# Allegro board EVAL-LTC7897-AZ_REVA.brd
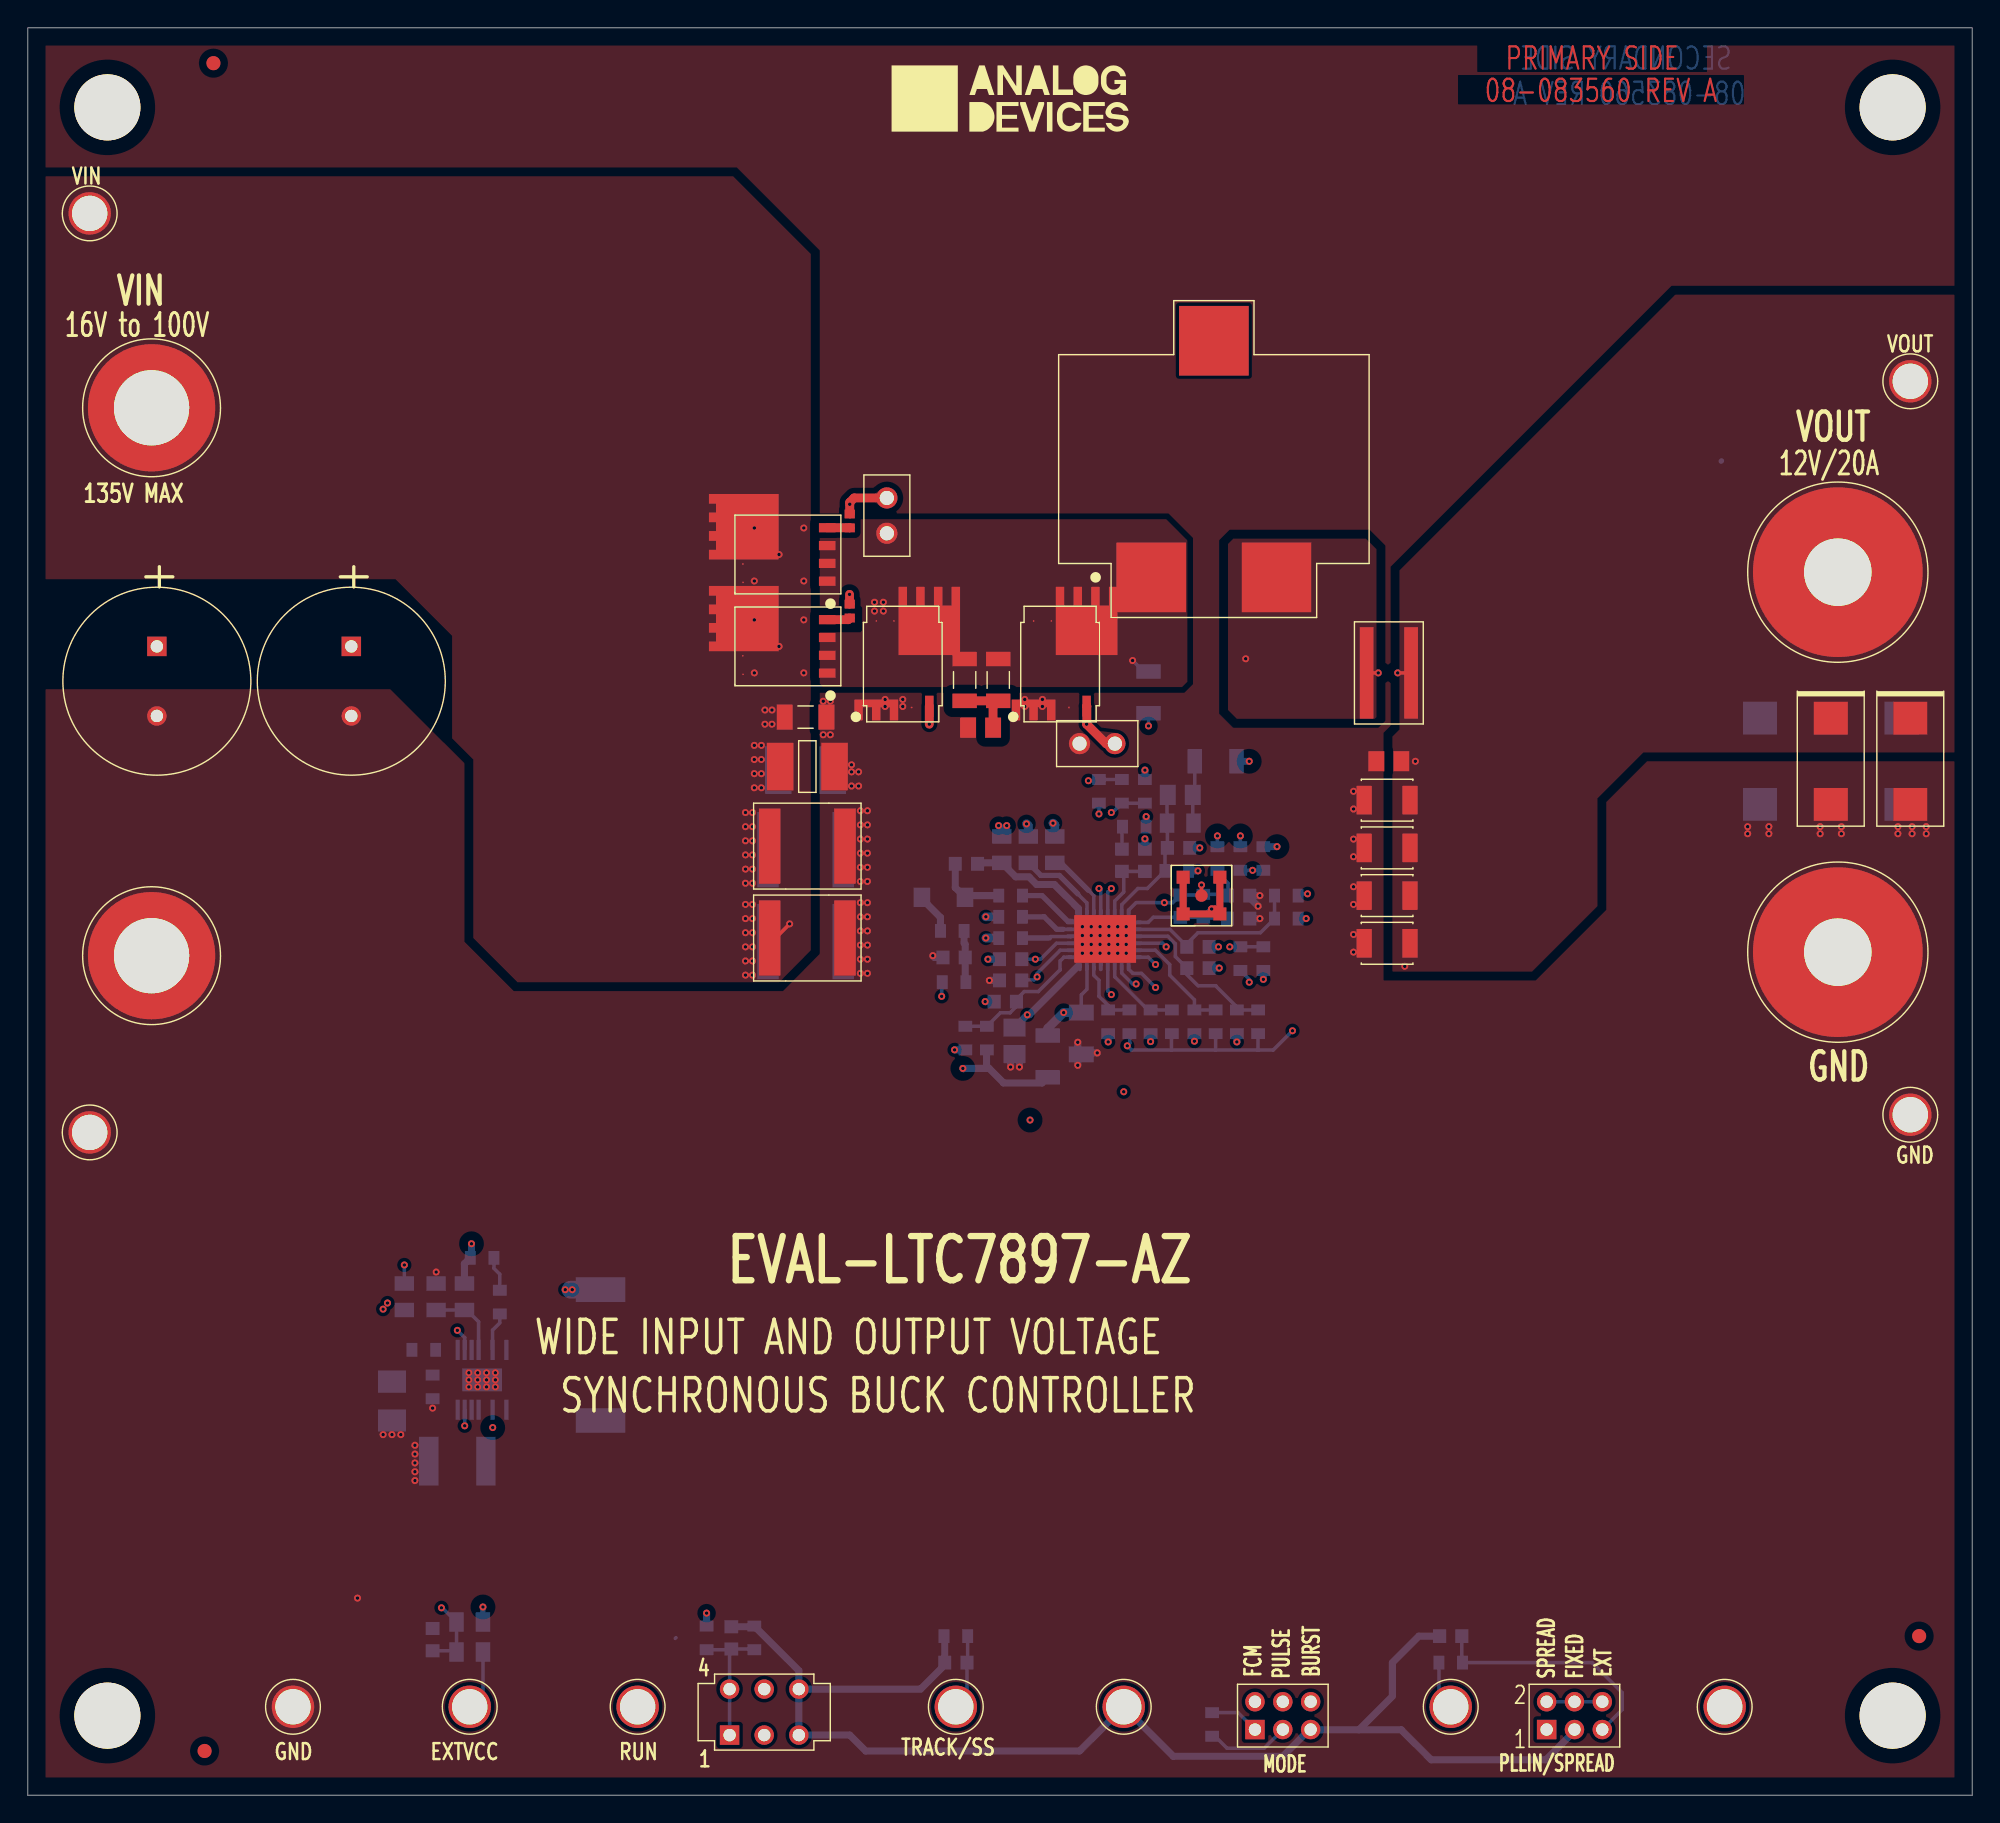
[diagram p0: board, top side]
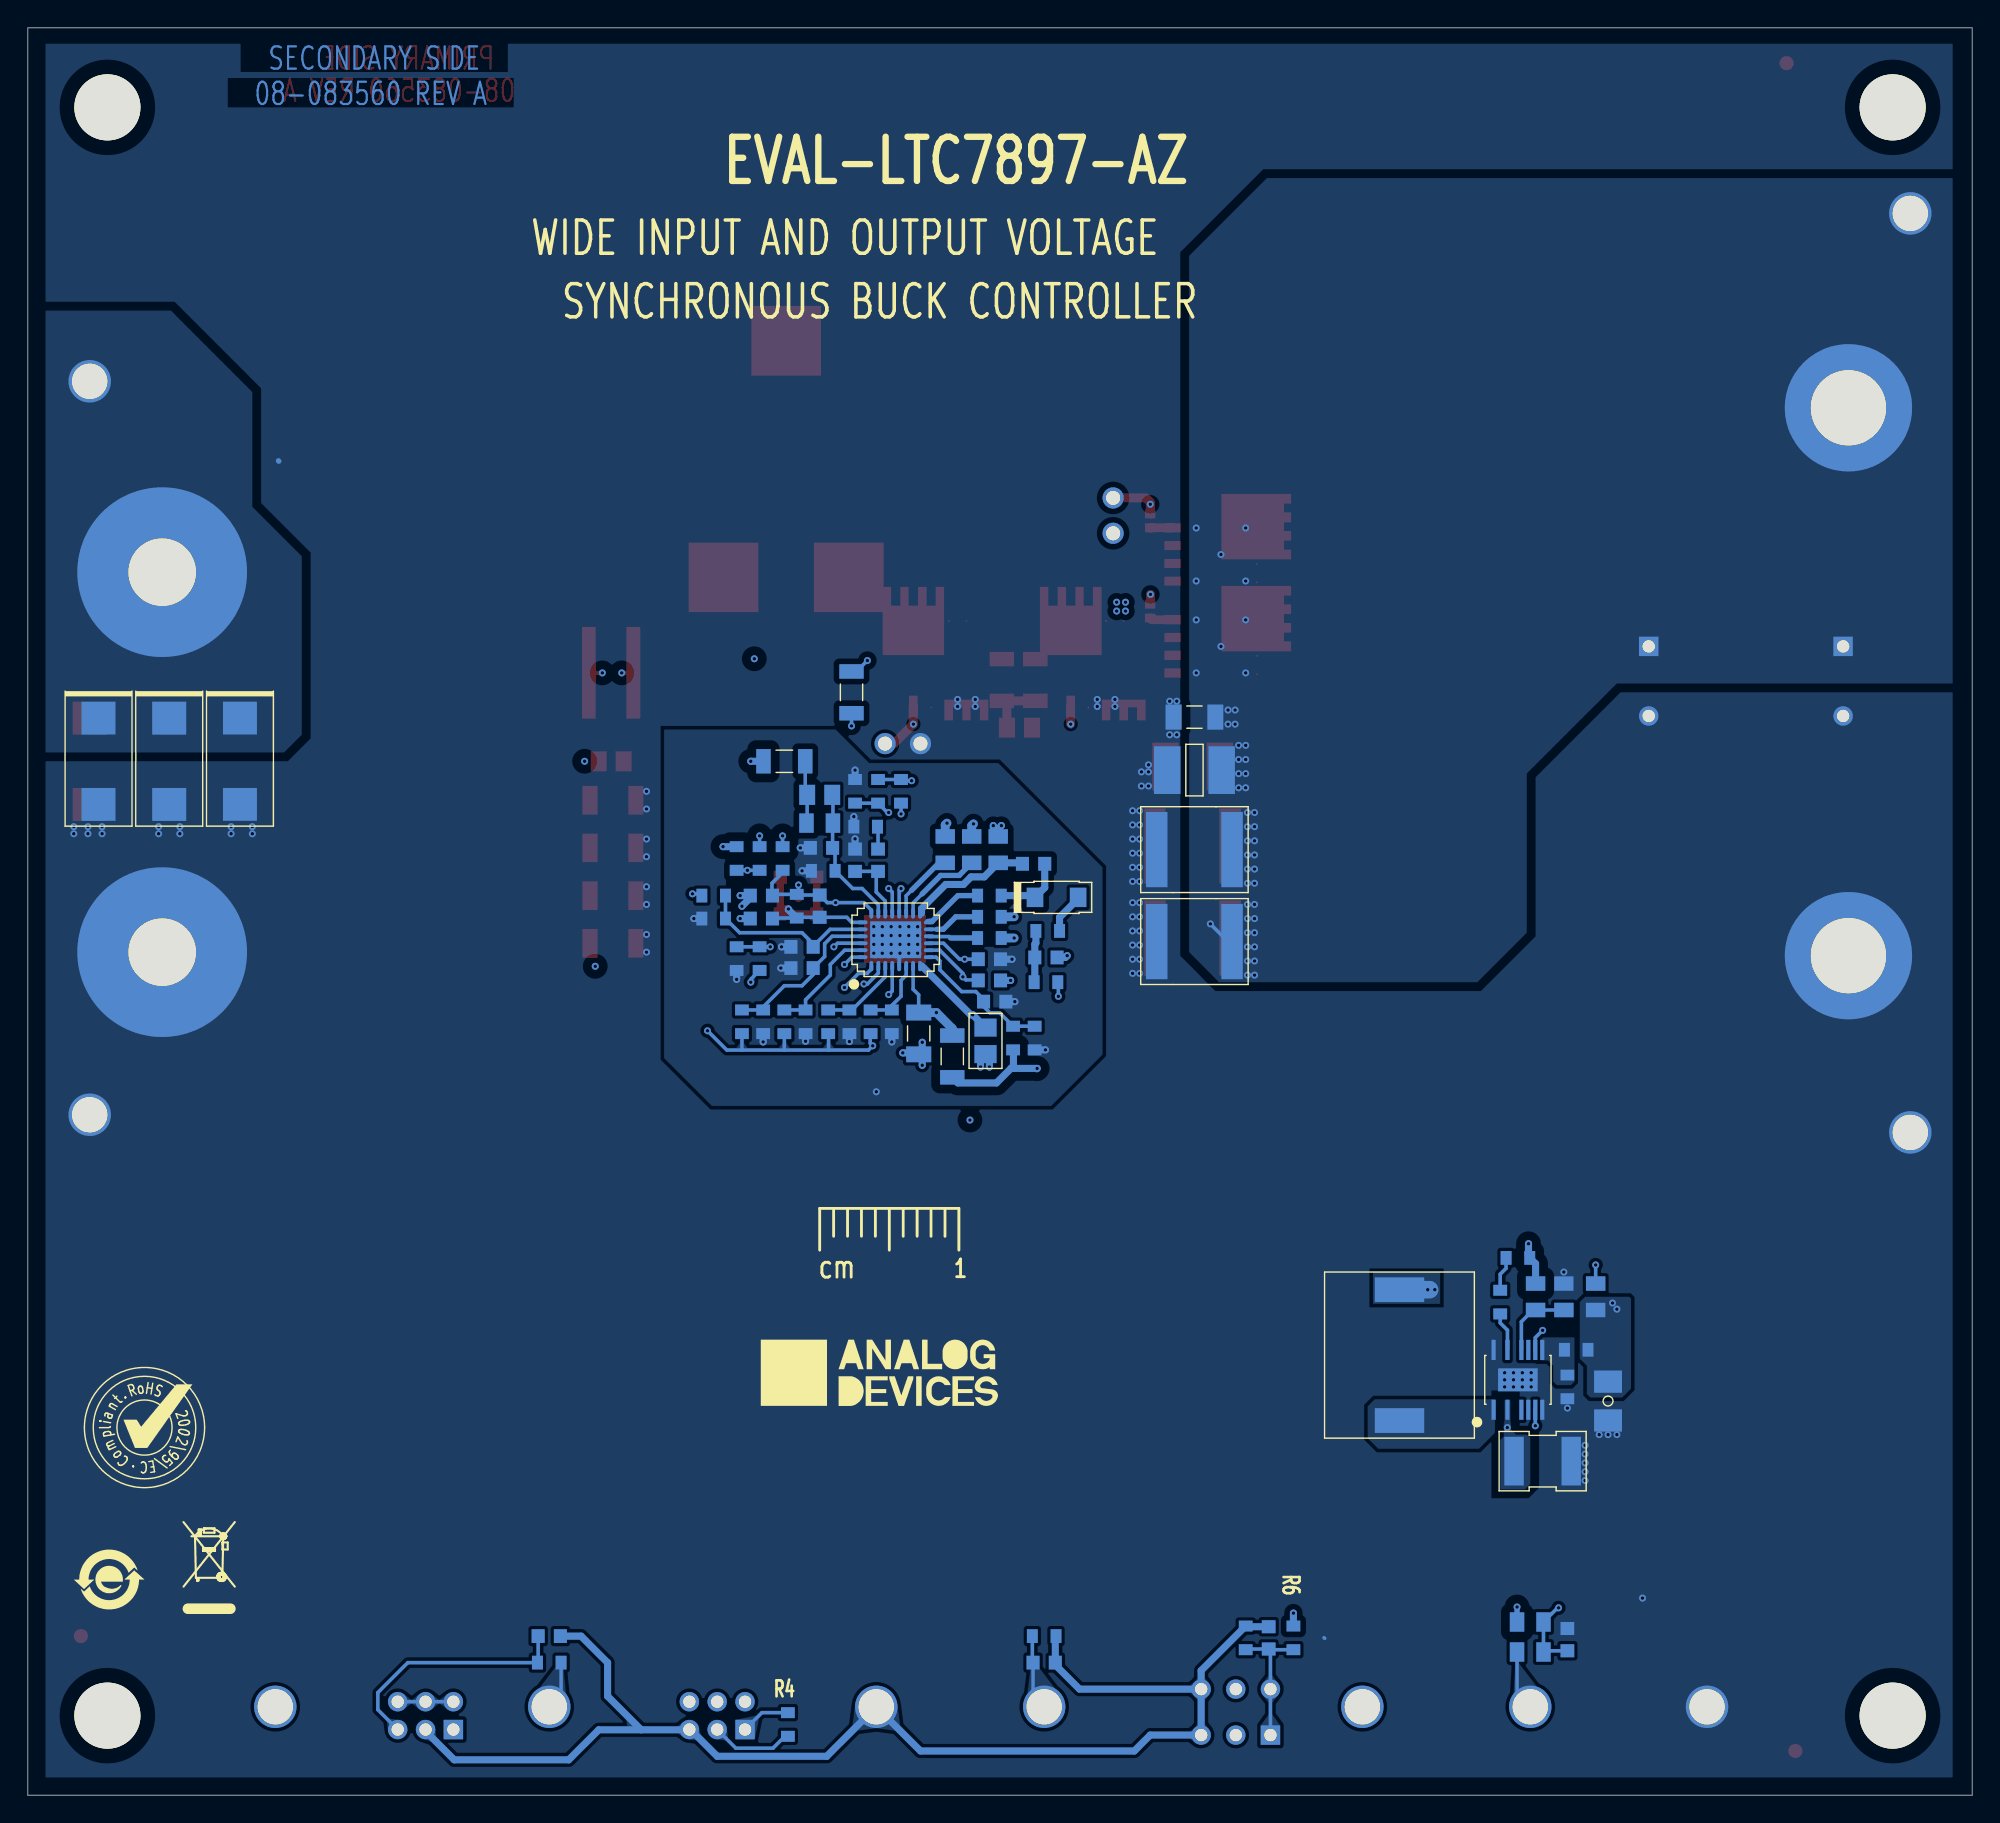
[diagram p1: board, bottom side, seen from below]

Outline 139.7 x 127 mm; copper layers: TOP, LAYER_2, LAYER_3, LAYER_4, LAYER_5, BOTTOM. Coordinates in mm from the lower left corner of the outline.
Outline path: 0,127 0,0 139.7,0 139.7,127 0,127

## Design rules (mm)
constraint set DEFAULT: min track width 0.254
net group _N309: nets _N97 _N309
net group VIN2: nets _N130 VIN2
net group BG: nets BG BG_X BG_X3
net group DRVUV: nets _N98 _N99 _N173 _N192 _N215 DRVUV DTCA DTCB INTVCC VPRG
net group EXTVCC: nets _N148 _N308 EXTVCC SNSN SNSP SW SWN UNNAMED_2_ADLT7809_I6_BOOST UNNAMED_2_ADLTC3639_I1_SW UNNAMED_2_ADLTC3639_I1_VFB UNNAMED_2_CAP_I88_N1 UNNAMED_2_CAP_I169_N1 UNNAMED_2_CNTP1P_I150_N1 UNNAMED_2_IND_I113_N2 VOUT VSOP

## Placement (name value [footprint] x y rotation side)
C1  TBD0603  [C0603]  84.07 59.44 0 bottom
C2  TBD0603  [C0603]  102.23 11.43 180 bottom
C3  47UF  [CPLRAD197D512H846LD24]  23.24 82.55 270 top
C4  0.1uF  [C0603]  66.67 9.53 180 bottom
C5  TBD0603  [C0603]  84.07 60.96 0 bottom
C6  47UF  [CPLRAD197D512H846LD24]  9.27 82.55 270 top
C7  2.2UF  [C2220H106]  56.01 68.2 0 top
C8  2.2UF  [C2220H106]  55.88 67.94 0 bottom
C9  TBD0805  [C0805]  82.8 71.88 180 bottom
C10  TBD0603  [C0603]  82.68 68.07 0 bottom
C11  0.1uF  [C1206]  75.69 54.74 270 bottom
C12  220pF  [C0603]  80.26 67.18 90 bottom
C13  6.8NF  [C0603]  78.61 67.18 90 bottom
C14  1uF  [C0603]  70.61 58.55 180 bottom
C15  4.7uF  [C0805H53]  70.89 54.2 270 bottom
C16  0.1uF  [C0603]  70.61 60.07 180 bottom
C17  1000pF  [C0603]  82.8 63.88 270 bottom
C18  TBD0603  [C0603]  50.55 11.3 90 bottom
C19  0.1uF  [C0603]  67.44 66.93 0 bottom
C20  0.1uF  [C0603]  66.55 60.2 180 bottom
C21  TBD0805  [C0805]  68.45 76.71 180 top
C22  1UF  [C1812H110]  55.88 73.66 0 bottom
C23  0.1uF  [C1206]  55.88 77.47 0 bottom
C24  1uF  [C0603]  29.08 11.18 90 bottom
C25  1UF  [C1812H110]  56.01 73.91 0 top
C26  0.1uF  [C1206]  55.88 77.47 0 top
C27  0.1UF  [C0805]  97.79 74.3 180 top
C28  22uF  [C1210H106]  97.66 71.5 180 top
C29  0.47UF  [C1812H71]  30.86 24 0 bottom
C30  22uF  [C1210H106]  97.66 68.07 180 top
C31  22uF  [C1210H106]  97.66 64.64 180 top
C32  100UF  [C7343-31]  124.46 74.3 270 bottom
C33  22uF  [C1210H106]  97.66 61.21 180 top
C34  100UF  [C7343-31]  129.54 74.3 270 bottom
C35  100UF  [C7343-31]  129.54 74.3 270 top
C36  100UF  [C7343-31]  134.62 74.3 270 bottom
C37  100UF  [C7343-31]  135.25 74.3 270 top
C39  4.7UF  [C1206H71]  26.16 28.32 270 bottom
C41  TBD0603  [C0603]  87 64.64 0 bottom
C42  TBD0603  [C0603]  87 62.99 180 bottom
C43  TBD0603  [C0603]  70.23 57.02 0 bottom
C44  2.2UF  [C2220H106]  56.01 61.59 0 top
C45  2.2UF  [C2220H106]  55.88 61.34 0 bottom
D1  PNE20010ERX  [SOD123W]  65.79 64.52 180 bottom
J1  575-4  [CNBANANAD312LD203]  8.89 99.69 0 top
J2  575-4  [CNBANANAD312LD203]  8.89 60.33 0 top
J3  KFH-032-10ET  [CNPEMKFH-032]  130.05 87.88 0 top
J4  KFH-032-10ET  [CNPEMKFH-032]  130.05 60.58 0 top
J5  0734152063  [CNSMASQ136H203]  84.33 64.64 0 top
JP1  62000621121  [CNTHMHDR2X3L236W157H248]  109.13 4.72 0 top
JP2  62000621121  [CNTHMHDR2X3L236W157H248]  88.17 4.72 0 top
L1  5.5UH  [LSML858W571H571]  85.22 96.01 0 top
L2  470UH  [LSML402W394H201]  41.15 31.62 90 bottom
NOREF  -  []  14.22 254.25 0 top
NOREF#2  -  []  0 127 0 top
NOREF#3  -  []  294.89 163.96 0 top
NOREF#4  -  [unnamed#2]  12.7 3.17 0 top
NOREF#5  -  []  112.39 -34.04 0 top
NOREF#6  -  []  302.51 96.77 0 top
NOREF#7  -  []  35.56 189.23 0 top
NOREF#8  -  [unnamed#2]  5.71 121.28 180 top
NOREF#9  -  []  244.35 286 0 top
NOREF#10  -  []  96.9 -16.26 0 top
NOREF#11  -  []  -76.2 -76.2 0 top
NOREF#12  -  [unnamed#2]  133.99 5.71 180 top
NOREF#13  -  []  70.61 121.92 0 top
NOREF#14  -  []  0 0 0 top
NOREF#15  -  []  249.05 252.09 0 top
NOREF#16  -  []  0 127 270 top
NOREF#17  -  []  -222.25 -146.05 0 top
NOREF#18  -  []  98.68 -22.73 0 top
NOREF#19  -  []  162.18 -27.18 0 top
NOREF#20  -  []  -76.2 -76.2 0 top
NOREF#21  -  []  96.9 -9.27 0 top
NOREF#22  -  []  289.43 215.01 0 top
NOREF#23  -  []  139.7 0 90 top
NOREF#24  -  [unnamed#2]  133.99 121.28 180 top
NOREF#25  -  []  -222.25 -146.05 0 top
NOREF#26  -  [unnamed#2]  5.71 5.71 180 top
NOREF#27  -  []  162.18 -17.27 0 top
NOREF#28  -  [unnamed#2]  13.34 124.46 0 top
NOREF#29  -  []  110.49 123.06 270 top
NOREF#30  -  [unnamed#2]  135.89 11.43 0 top
NOREF#31  -  []  139.7 127 180 top
NOREF#32  -  []  -76.2 -76.2 0 top
NOREF#33  -  []  139.7 0 90 top
NOREF#34  -  []  78.49 30.35 180 bottom
NOREF#35  -  []  126.87 13.08 180 bottom
NOREF#36  -  []  83.44 39.24 180 bottom
NOREF#37  -  []  133.86 15.49 180 bottom
NOREF#38  -  []  131.32 26.42 180 bottom
P1  PEC02SAAN  [CNSULLINSPEC02SAAN]  61.72 93.22 270 top
P3  PEC02SAAN  [CNSULLINSPEC02SAAN]  78.11 75.56 180 top
Q1  BSC110N15NS5ATMA1  [SON8]  54.61 82.55 90 top
Q2  ISC055N15NM6ATMA1  [PG-TDSON-8_B]  62.87 81.28 0 top
Q3  BSC110N15NS5ATMA1  [SON8]  54.61 89.15 90 top
Q4  ISC055N15NM6ATMA1  [PG-TDSON-8_B]  74.17 81.28 0 top
R1  1K  [R0603]  102.23 9.53 0 bottom
R2  TBD0603  [R0603]  66.67 11.43 180 bottom
R3  0  [R0402]  59.05 91.57 270 top
R4  100K  [R0603]  85.09 5.08 270 bottom
R5  90.9  [R0603]  84.45 63.88 270 bottom
R6  1MEG  [R0603]  48.77 11.3 270 bottom
R7  140K  [R0805]  82.8 69.85 180 bottom
R8  10K  [R0603]  82.55 66.42 0 bottom
R9  TBD0603  [R0603]  78.61 72.14 270 bottom
R10  TBD0603  [R0603]  80.26 72.14 90 bottom
R11  8.06K  [R0603]  79.5 69.6 0 bottom
R12  0  [R1206]  73.28 53.09 90 bottom
R13  187K  [R0603]  80.67 55.58 270 bottom
R14  TBD0603  [R0603]  82.19 55.58 90 bottom
R15  100K  [R0603]  76.96 72.14 90 bottom
R16  0  [R0603]  87.12 60.11 90 bottom
R17  TBD0603  [R0603]  88.77 60.11 270 bottom
R18  0  [R0603]  70.61 64.64 180 bottom
R19  0  [R0603]  70.61 61.59 180 bottom
R20  0  [R0603]  70.61 63.12 180 bottom
R21  2  [R0805]  73.79 67.94 90 bottom
R22  0  [R0805]  71.88 67.94 90 bottom
R23  0  [R0603]  66.42 62.1 0 bottom
R24  TBD1206  [R1206]  69.72 80.14 270 top
R25  0  [R0603]  66.55 58.42 180 bottom
R26  0  [R0805]  69.98 67.94 90 bottom
R27  0  [R0805]  31.75 12.45 180 bottom
R28  0  [R0805]  31.75 10.29 0 bottom
R29  TBD1206  [R1206]  80.52 79.25 270 bottom
R30  TBD0603  [R0603]  88.77 67.31 270 bottom
R31  10  [R0603]  85.47 67.31 270 bottom
R32  0.002  [R1225H28]  97.79 80.64 0 top
R33  0  [R0603]  87.12 67.31 270 bottom
R34  2MEG  [R0603]  32.64 38.61 0 bottom
R35  TBD0805  [R0805]  31.37 35.81 270 bottom
R36  0  [R0603]  33.91 35.43 270 bottom
R37  0  [R0805]  29.34 35.81 270 bottom
R38  0  [R0805]  27.05 35.81 270 bottom
R39  267K  [R0603]  28.45 32 0 bottom
R40  196K  [R0603]  29.08 29.34 270 bottom
R41  0  [R0402]  59.05 85.09 270 top
R42  0  [R1206]  85.34 74.3 0 bottom
R43  0  [R0603]  85.34 55.58 90 bottom
R44  0  [R0603]  83.82 55.58 270 bottom
R45  0  [R0603]  88.39 55.58 90 bottom
R46  18.2K  [R0603]  86.87 55.58 270 bottom
R47  TBD0603  [R0603]  68.91 54.41 90 bottom
R48  0  [R0603]  67.36 54.41 270 bottom
R49  TBD1206  [R1206]  67.31 80.14 270 top
R52  TBD0603  [R0603]  79.15 55.58 90 bottom
R53  TBD0603  [R0603]  77.62 55.58 270 bottom
R54  TBD0603  [R0603]  90.42 64.64 180 bottom
R55  10K  [R0603]  90.42 62.99 0 bottom
R56  84.5K  [R0603]  52.2 11.3 90 bottom
SW1  JS202011CQN  [SWTHL354W142H217]  50.42 4.32 0 top
TP1  2501-2-00-80-00-00-07-0  [CNMILLMAX2501]  43.81 6.35 0 top
TP2  2501-2-00-80-00-00-07-0  [CNMILLMAX2501]  66.67 6.35 0 top
TP3  2501-2-00-80-00-00-07-0  [CNMILLMAX2501]  4.45 113.67 0 top
TP4  2501-2-00-80-00-00-07-0  [CNMILLMAX2501]  4.45 47.62 0 top
TP5  2501-2-00-80-00-00-07-0  [CNMILLMAX2501]  135.25 48.9 0 top
TP6  2501-2-00-80-00-00-07-0  [CNMILLMAX2501]  102.23 6.35 0 top
TP7  2501-2-00-80-00-00-07-0  [CNMILLMAX2501]  121.92 6.35 0 top
TP8  2501-2-00-80-00-00-07-0  [CNMILLMAX2501]  135.25 101.6 0 top
TP9  2501-2-00-80-00-00-07-0  [CNMILLMAX2501]  31.75 6.35 0 top
TP10  2501-2-00-80-00-00-07-0  [CNMILLMAX2501]  19.05 6.35 0 top
TP11  2501-2-00-80-00-00-07-0  [CNMILLMAX2501]  78.74 6.35 0 top
U1  LTC7897RUFD#PBF  [QFN28_5X4_PAD3_65X2_65_05-08-1712]  77.34 61.47 180 bottom
U2  LTC3639EMSE#PBF  [MSOP16_PAD2_845X1_651_12P_05-08-1871]  32.64 29.84 180 bottom

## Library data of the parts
C1 C2 C5 C10 C18 C41-C43 = CAP: User Part Number: UPN; alternate symbols: (C0603)
C3 C6 = CAPP: User Part Number: UPN; Tolerance: 20; alternate symbols: (CPLRAD197D512H846LD24); tolerance: 20
C4 C13 C14 C16 C19 C20 C24 = CAP: User Part Number: UPN; Tolerance: 10; alternate symbols: (C0603); tolerance: 10
C7 C8 C44 C45 = CAP: User Part Number: UPN; Tolerance: 10; alternate symbols: (C2220H106); tolerance: 10
C9 C21 = CAP: User Part Number: UPN; alternate symbols: (C0805)
C11 = CAP: User Part Number: UPN; Tolerance: 5; alternate symbols: (C1206); tolerance: 5
C12 C17 = CAP: User Part Number: UPN; Tolerance: 5; alternate symbols: (C0603); tolerance: 5
C15 = CAP: Tolerance: 10; User Part Number: UPN; alternate symbols: (C0805H53); tolerance: 10
C22 C25 = CAP: Tolerance: 20; User Part Number: UPN; alternate symbols: (C1812H110); tolerance: 20
C23 C26 = CAP: User Part Number: UPN; Tolerance: 10; alternate symbols: (C1206); tolerance: 10
C27 = CAP: User Part Number: UPN; Tolerance: 10; alternate symbols: (C0805); tolerance: 10
C28 C30 C31 C33 = CAP: Tolerance: 10; User Part Number: UPN; alternate symbols: (C1210H106); tolerance: 10
C29 = CAP: Tolerance: 10; User Part Number: UPN; alternate symbols: (C1812H71); tolerance: 10
C32 C34-C37 = CAPP: Tolerance: 20; User Part Number: UPN; alternate symbols: (C7343-31); tolerance: 20
C39 = CAP: Tolerance: 10; User Part Number: UPN; alternate symbols: (C1206H71); tolerance: 10
D1 = DIO: User Part Number: UPN; Tolerance: N/A; alternate symbols: (SOD123W); tolerance: N/A
J1 J2 = CNTP1P: Tolerance: N/A; User Part Number: UPN; alternate symbols: (CNBANANAD312LD203); tolerance: N/A
J3 J4 = CN1P: User Part Number: UPN; Tolerance: N/A; alternate symbols: (CNPEMKFH-032); tolerance: N/A
J5 = CNBNC5P: Tolerance: N/A; User Part Number: UPN; alternate symbols: (CNSMASQ136H203); tolerance: N/A
JP1 JP2 = CN6P_JMPRSHRT: User Part Number: UPN; Tolerance: N/A; alternate symbols: (CNTHMHDR2X3L236W157H248); tolerance: N/A
L1 = IND: Tolerance: 15; User Part Number: UPN; alternate symbols: (LSML858W571H571); tolerance: 15
L2 = IND: Tolerance: 10; User Part Number: UPN; alternate symbols: (LSML402W394H201); tolerance: 10
P1 P3 = CN2P: Tolerance: N/A; User Part Number: UPN; alternate symbols: (CNSULLINSPEC02SAAN); tolerance: N/A
Q1 Q3 = TRANNMOSFET8P: Tolerance: N/A; User Part Number: UPN; alternate symbols: (SON8); tolerance: N/A
Q2 Q4 = TRANNMOSFET8P: Tolerance: N/A; User Part Number: UPN; alternate symbols: (PG-TDSON-8_B); tolerance: N/A
R1 R4-R6 R8 R11 R13 R15 R31 R34 R39 R40 R46 R55 R56 = RES: User Part Number: UPN; Tolerance: 1; alternate symbols: (R0603); tolerance: 1
R2 R9 R10 R14 R17 R30 R47 R52-R54 = RES: User Part Number: UPN; alternate symbols: (R0603)
R3 R41 = RES: User Part Number: UPN; Tolerance: JUMPER; alternate symbols: (R0402); tolerance: JUMPER
R7 = RES: User Part Number: UPN; Tolerance: 1; alternate symbols: (R0805); tolerance: 1
R12 R42 = RES: User Part Number: UPN; Tolerance: JUMPER; alternate symbols: (R1206); tolerance: JUMPER
R16 R18-R20 R23 R25 R33 R36 R43-R45 R48 = RES: User Part Number: UPN; Tolerance: JUMPER; alternate symbols: (R0603); tolerance: JUMPER
R21 = RES: User Part Number: UPN; Tolerance: 5; alternate symbols: (R0805); tolerance: 5
R22 R26-R28 R37 R38 = RES: User Part Number: UPN; Tolerance: N/A; alternate symbols: (R0805); tolerance: N/A
R24 R29 R49 = RES: User Part Number: UPN; alternate symbols: (R1206)
R32 = RES: User Part Number: UPN; Tolerance: 2; alternate symbols: (R1225H28); tolerance: 2
R35 = RES: User Part Number: UPN; alternate symbols: (R0805)
SW1 = SWDPDT_V5: Tolerance: N/A; User Part Number: UPN; alternate symbols: (SWTHL354W142H217); tolerance: N/A
TP1-TP11 = CNTP1P: User Part Number: UPN; Tolerance: N/A; alternate symbols: (CNMILLMAX2501); tolerance: N/A
U1 = ADLTC7897: User Part Number: UPN; Tolerance: N/A; alternate symbols: (QFN28_5X4_PAD3_65X2_65_05-08-1712); tolerance: N/A
U2 = ADLTC3639: Tolerance: N/A; User Part Number: UPN; alternate symbols: (MSOP16_PAD2_845X1_651_12P_05-08-1871); tolerance: N/A

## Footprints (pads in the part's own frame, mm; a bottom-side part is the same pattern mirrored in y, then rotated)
C0603
  rect 0.94x0.991 smd: 1(-0.8,0) 2(0.8,0)
C0805
  rect 1.143x1.448 smd: 1(-0.9,0) 2(0.9,0)
C0805H53
  rect 1.295x1.6 smd: 1(-0.953,0) 2(0.953,0)
C1206
  rect 1.143x1.803 smd: 1(-1.5,0) 2(1.5,0)
C1206H71
  rect 1.6x2.007 smd: 1(-1.397,0) 2(1.397,0)
C1210H106
  rect 1.092x2.057 smd: 1(-1.646,0) 2(1.646,0)
C1812H71
  rect 1.397x3.505 smd: 1(-2.05,0) 2(2.05,0)
C1812H110
  rect 1.905x3.429 smd: 1(-1.956,0) 2(1.956,0)
C2220H106
  rect 1.549x5.41 smd: 1(-2.705,0) 2(2.705,0)
C7343-31
  rect 2.362x2.438 smd: N(3.1,0) P(-3.1,0)
CNBANANAD312LD203
  round 9.144 hole 5.41: 1(0,0)
CNMILLMAX2501
  round 3.048 hole 2.54: 1(0,0)
CNPEMKFH-032
  round 12.192 hole 4.851: 1(0,0)
CNSMASQ136H203
  round 0.889 smd: 1(0,0)
  rect 0.94x0.94 smd: 2(-1.32,-1.32) 3(1.32,-1.32) 4(1.32,1.32) 5(-1.32,1.32)
CNSULLINSPEC02SAAN
  round 1.524 hole 1.016: 1(0,0) 2(2.54,0)
CNTHMHDR2X3L236W157H248
  rect 1.397x1.397 hole 0.889: 1(0,0)
  round 1.397 hole 0.889: 2(0,2) 3(2,0) 4(2,2) 5(4,0) 6(4,2)
CPLRAD197D512H846LD24
  round 1.397 hole 0.889: N(5,0)
  rect 1.397x1.397 hole 0.889: P(0,0)
LSML402W394H201
  rect 1.778x3.556 smd: 1(-4.7,0) 2(4.7,0)
LSML858W571H571
  rect 5.004x5.004 smd: (0,8.502) 1(-4.502,-8.502) 2(4.502,-8.502)
MSOP16_PAD2_845X1_651_12P_05-08-1871
  rect 0.305x1.448 smd: 1(-1.75,-2.15) 3(-0.75,-2.15) 5(0.25,-2.15) 6(0.75,-2.15) 7(1.25,-2.15) 8(1.75,-2.15) 9(1.75,2.15) 10(1.25,2.15) 11(0.75,2.15) 12(0.25,2.15) 14(-0.75,2.15) 16(-1.75,2.15)
  rect 2.845x1.651 smd: 17(0,0)
PG-TDSON-8_B
  custom 0.375x0.375 smd: 1(-1.905,-3.3)
  round 0.127 smd: 2(-0.635,-3.12) 3(0.635,-3.12) 6(0.635,3.097) 7(-0.635,3.097) 8(-1.905,3.097)
  rect 0.61x1.499 smd: 4(1.905,-3.021)
  custom 1.105x1.105 smd: 5(1.905,3.097)
QFN28_5X4_PAD3_65X2_65_05-08-1712
  oval 0.279x0.737 smd: 1(-1.75,-1.893) 2(-1.25,-1.893) 3(-0.75,-1.893) 4(-0.25,-1.893) 5(0.25,-1.893) 6(0.75,-1.893) 7(1.25,-1.893) 8(1.75,-1.893) 15(1.75,1.893) 16(1.25,1.893) 17(0.75,1.893) 18(0.25,1.893) 19(-0.25,1.893) 20(-0.75,1.893) 21(-1.25,1.893) 22(-1.75,1.893)
  oval 0.737x0.279 smd: 9(2.393,-1.25) 10(2.393,-0.75) 11(2.393,-0.25) 12(2.393,0.25) 13(2.393,0.75) 14(2.393,1.25) 23(-2.393,1.25) 24(-2.393,0.75) 25(-2.393,0.25) 26(-2.393,-0.25) 27(-2.393,-0.75) 28(-2.393,-1.25)
  rect 3.658x2.642 smd: 29(0,0)
R0402
  rect 0.635x0.737 smd: 1(-0.5,0) 2(0.5,0)
R0603
  rect 0.787x0.991 smd: 1(-0.85,0) 2(0.85,0)
R0805
  rect 1.041x1.397 smd: 1(-0.95,0) 2(0.95,0)
R1206
  rect 1.041x1.753 smd: 1(-1.5,0) 2(1.5,0)
R1225H28
  rect 0.991x6.579 smd: 1(-1.595,0) 2(1.595,0)
SOD123W
  rect 1.194x1.397 smd: A(1.549,0) C(-1.549,0)
SON8
  rect 0.66x1.194 smd: 1(-1.92,-2.828) 2(-0.64,-2.828) 3(0.64,-2.828) 4(1.92,-2.828)
  custom 1.175x1.175 smd: 5(2,3.171)
  round 0.127 smd: 6(0.678,3.211) 7(-0.68,3.236) 8(-2.002,3.223)
SWTHL354W142H217
  rect 1.397x1.397 hole 0.889: 1(0,0)
  round 1.397 hole 0.889: 2(2.489,0) 3(4.978,0) 4(0,3.302) 5(2.489,3.302) 6(4.978,3.302)
unnamed#2
  round 1.016 smd: (0,0)

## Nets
GND_POWER: C3.N(N2) C6.N(N2) C7.2(N2) C8.2(N2) C11.2(N2) C14.2(N2) C15.2(N2) C20.2(N2) C21.2(N2) C22.2(N2) C23.2(N2) C24.2(N2) C25.2(N2) C26.2(N2) C27.2(N2) C28.2(N2) C29.1 C30.2(N2) C31.2(N2) C32.N(N2) C33.2(N2) C34.N(N2) C35.N(N2) C36.N(N2) C37.N(N2) C39.2(N2) C41.2(N2) C42.1 C44.2(N2) C45.2(N2) J2.1(N1) J4.1(N1) P3.2(N2) Q2.1 Q2.2 Q2.3(S3) Q4.1 Q4.2 Q4.3(S3) R37.1 R40.2(N2) TP4.1(N1) TP5.1(N1) TP10.1(N1) U2.6(VPRG2) U2.8 U2.16 U2.17
GND_SIGNAL: C1.2(N2) C2.2(N2) C4.2(N2) C5.2(N2) C10.2(N2) C12.2(N2) C16.2(N2) C18.2(N2) C43.1 JP1.3 JP2.5 R2.2(N2) R8.2(N2) R10.2(N2) R11.2(N2) R13.2(N2) R17.2(N2) R44.2(N2) R46.2(N2) R48.2(N2) R53.2(N2) R55.2(N2) R56.2(N2) SW1.3 SW1.6(NO2) TP11.1(N1) U1.5 U1.29
VIN: C3.P C6.P C7.1 C8.1 C22.1 C23.1 C25.1 C26.1 C29.2(N2) C44.1 C45.1 J1.1(N1) Q1.5 Q1.6 Q1.7 Q1.8 Q3.5 Q3.6 Q3.7 Q3.8 R12.1 R34.1 R35.1 R47.1 TP3.1(N1) U2.3
VIN2: C11.1 R6.1 R12.2(N2) U1.7
_N7: C43.2(N2) R47.2(N2) R48.1 U1.9
_N30: U2.7 U2.10
_N97: R1.1 TP6.1(N1)
_N98: R13.1 R14.2(N2) U1.3
_N99: JP2.3 R4.2(N2)
_N100: JP2.2 JP2.4 JP2.6(S6) U1.2
_N104: SW1.2 SW1.5 TP1.1(N1) U1.28
_N130: C18.1 R6.2(N2) R56.1 SW1.1 SW1.4
_N143: C4.1 R2.1 TP2.1(N1) U1.4
_N148: C9.2(N2) C10.1 R7.2(N2) R8.1 U1.21
_N161: C13.2(N2) R11.1
_N165: C12.1 C13.1 U1.20
_N173: R9.2(N2) R10.1 U1.19
_N186: JP1.2 JP1.4 JP1.6(S6) U1.1
_N192: R15.1 TP7.1(N1) U1.18
_N215: R16.2(N2) R17.1 U1.26
_N308: C21.1 R24.2(N2) R49.2(N2)
_N309: C2.1 JP1.5 R1.2(N2)
BG: P3.1 Q2.4 Q4.4 R19.2(N2) R20.2(N2)
BG_X: R19.1 U1.12
BG_X3: R20.1 U1.13
DRVCC: C15.1 R25.2(N2) U1.8
DRVUV: R43.2(N2) R44.1 U1.27
DTCA: C1.1 R45.2(N2) R46.1 U1.25
DTCB: C5.1 R54.2(N2) R55.1 U1.24
EXTVCC: C14.1 C24.1 R27.2(N2) R28.1 R38.1 U1.10
INTVCC: C16.1 JP1.1 JP2.1 R4.1 R9.1 R14.1 R15.2(N2) R16.1 R43.1 R45.1 R52.1 R54.1 U1.11
SNSN: C17.2(N2) C42.2(N2) J5.2 J5.3 J5.4 J5.5(SH4) R5.2(N2) R30.2(N2) R33.2(N2) U1.23
SNSP: C17.1 C41.1 J5.1 R5.1 R29.2(N2) R31.2(N2) U1.22
SW: C19.2(N2) R26.1 U1.15
SWN: L1.1 P1.2(N2) Q1.1 Q1.2 Q1.3(S3) Q2.5 Q2.6 Q2.7 Q2.8 Q3.1 Q3.2 Q3.3(S3) Q4.5 Q4.6 Q4.7 Q4.8 R24.1 R26.2(N2) R29.1 R49.1
TG: P1.1 R3.1 R21.2(N2) R22.2(N2) R41.1
TG_X: R21.1 U1.17
TG_X1: Q3.4 R3.2(N2)
TG_X2: Q1.4 R41.2(N2)
TG_X3: R22.1 U1.16
UNNAMED_2_ADLT7809_I6_BOOST: R18.1 U1.14
UNNAMED_2_ADLTC3639_I1_OVLO: R35.2(N2) R37.2(N2) U2.12
UNNAMED_2_ADLTC3639_I1_RUN: R36.2(N2) U2.14
UNNAMED_2_ADLTC3639_I1_SW: L2.1 U2.1
UNNAMED_2_ADLTC3639_I1_VFB: R39.2(N2) R40.1 U2.9
UNNAMED_2_CAP_I88_N1: C19.1 D1.C R18.2(N2)
UNNAMED_2_CAP_I91_N1: C20.1 R23.2(N2) R25.1
UNNAMED_2_CAP_I169_N1: C39.1 L2.2(N2) R38.2(N2) R39.1
UNNAMED_2_CNTP1P_I150_N1: R28.2(N2) TP9.1(N1)
UNNAMED_2_DIO_I86_P: D1.A(P) R23.1
UNNAMED_2_IND_I113_N2: L1.2(N2) R30.1 R31.1 R32.1
UNNAMED_2_RES_I159_N2: R34.2(N2) R36.1
VOUT: C27.1 C28.1 C30.1 C31.1 C32.P C33.1 C34.P C35.P C36.P C37.P J3.1(N1) R27.1 R32.2(N2) R33.1 R42.2(N2) TP8.1(N1)
VPRG: R52.2(N2) R53.1 U1.6(VPRG)
VSOP: C9.1 R7.1 R42.1

Pads without a net: U2 5 11

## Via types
v1: diameter 0.508, hole 0.254, TOP to BOTTOM, 247 vias

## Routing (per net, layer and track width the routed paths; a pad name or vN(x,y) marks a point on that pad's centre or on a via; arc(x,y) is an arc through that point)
GND_POWER: length 9.2
  BOTTOM w0.254: 46.57,11.32 46.52,11.27
  BOTTOM w0.381: 121.67,95.86 121.69,95.89
  BOTTOM w0.508: v1(65.02,60.33) 65.15,60.2 C20.2 ; C11.2 75.8,53.34 v1(76.83,53.34) ; C11.2 75.44,52.98 v1(75.44,52.45) ; C11.2 75.44,53.49 v1(75.44,54.1) ; v1(70.61,52.32) 70.61,52.97 C15.2 71.25,52.9 v1(71.25,52.32) ; v1(88.52,64.64) C41.2 87.8,64.48 v1(88.39,63.88) ; C42.1 v1(88.52,62.99) ; C14.2 v1(69.09,58.55)
  vias: v1(23.69,14.16) v1(25.53,25.91) v1(26.16,25.91) v1(26.8,25.91) v1(27.81,25.15) v1(27.81,24.51) v1(27.81,23.88) v1(27.81,23.24) v1(27.81,22.61) v1(29.08,27.81) v1(29.34,37.59) v1(31.69,30.35) v1(31.69,29.84) v1(31.69,29.34) v1(32.32,30.35) v1(32.32,29.84) v1(32.32,29.34) v1(32.96,30.35) v1(32.96,29.84) v1(32.96,29.34) v1(33.59,30.35) v1(33.59,29.84) v1(33.59,29.34) v1(57.15,78.61) v1(57.15,76.2) v1(57.66,78.61) v1(57.66,76.2) v1(59.18,74.04) v1(59.18,73.53) v1(59.18,72.52) v1(59.69,73.53) v1(59.69,72.52) v1(59.82,70.74) v1(59.82,69.72) v1(59.82,68.71) v1(59.82,67.69) v1(59.82,66.67) v1(59.82,65.66) v1(59.82,64.14) v1(59.82,63.12) v1(59.82,62.1) v1(59.82,61.09) v1(59.82,60.07) v1(59.82,59.05) v1(60.33,70.74) v1(60.33,69.72) v1(60.33,68.71) v1(60.33,67.69) v1(60.33,66.67) v1(60.33,65.66) v1(60.33,64.14) v1(60.33,63.12) v1(60.33,62.1) v1(60.33,61.09) v1(60.33,60.07) v1(60.33,59.05) v1(61.59,78.74) v1(61.59,78.23) v1(62.87,78.74) v1(62.87,78.23) v1(71.63,78.74) v1(71.63,78.23) v1(72.9,78.74) v1(72.9,78.23) v1(95.25,72.14) v1(95.25,70.87) v1(95.25,68.71) v1(95.25,67.44) v1(95.25,65.28) v1(95.25,64.01) v1(95.25,61.85) v1(95.25,60.58) v1(123.57,69.6) v1(123.57,69.09) v1(125.09,69.6) v1(125.09,69.09) v1(128.78,69.6) v1(128.78,69.09) v1(130.3,69.6) v1(130.3,69.09) v1(134.37,69.6) v1(134.37,69.09) v1(135.38,69.6) v1(135.38,69.09) v1(136.4,69.6) v1(136.4,69.09)
GND_SIGNAL: length 151.8
  LAYER_3 w0.508: TP11.1 v1(78.74,50.55)
  BOTTOM w0.254: v1(77.04,60.5) 77.04,60.24 77.09,60.18 U1.5
  BOTTOM w0.508: SW1.6 64.14,7.62 65.87,9.36 C4.2 65.87,11.38 R2.2 ; SW1.6 55.4,8.95 R56.2 52.15,12.1 C18.2 ; SW1.6 SW1.3 59.05,4.32 60.2,3.17 75.56,3.17 TP11.1 82.3,2.79 90.17,2.79 92.09,4.72 JP2.5 92.19,4.7 95.63,4.7 ; C12.2 v1(80.26,68.72) ; v1(68.78,57.02) C43.1 69.56,57.02 ; C2.2 99.95,11.43 98.04,9.53 98.04,7.11 95.63,4.7 ; R53.2 v1(77.62,54.13) ; 95.63,4.7 98.68,4.7 100.84,2.54 109.07,2.54 111.12,4.6 JP1.3 ; C10.2 v1(84.2,68.07) ; R48.2 v1(66.59,53.56) ; R8.2 v1(84.07,66.42) ; C5.2 v1(85.55,60.96) ; R11.2 v1(80.35,70.32) ; R13.2 v1(80.67,54.15) ; R55.2 v1(91.85,62.99) ; R17.2 v1(88.77,58.62) ; R10.2 v1(80.26,73.66) ; R46.2 v1(86.87,54.13) ; C16.2 v1(68.99,60.07) ; R44.2 v1(83.82,54.18) ; C1.2 v1(85.6,59.44)
  vias: v1(75.77,62.41) v1(75.77,61.77) v1(75.77,61.14) v1(75.77,60.5) v1(76.4,62.41) v1(76.4,61.77) v1(76.4,61.14) v1(76.4,60.5) v1(77.04,62.41) v1(77.04,61.77) v1(77.04,61.14) v1(77.67,62.41) v1(77.67,61.77) v1(77.67,61.14) v1(77.67,60.5) v1(78.31,62.41) v1(78.31,61.77) v1(78.31,61.14) v1(78.31,60.5) v1(78.92,62.41) v1(78.92,61.77) v1(78.92,61.14) v1(78.92,60.5)
VIN: length 88.8
  TOP w0.254: C44.1 53.72,61.59 v1(54.74,62.61)
  LAYER_3 w0.508: v1(31.88,39.62) 33.15,40.89 57.15,40.89 67.18,50.93 v1(67.18,52.22) 64.11,52.22 54.74,61.59 v1(54.74,62.61)
  LAYER_4 w0.508: v1(33.4,26.42) 34.8,27.81 34.8,36.7 v1(31.88,39.62)
  BOTTOM w0.254: v1(54.74,62.61) 53.47,61.34 C45.1
  BOTTOM w0.508: 69.06,52.22 v1(67.18,52.22) 67.21,52.2 ; 69.06,52.22 68.88,52.4 68.88,53.53 R47.1 ; 69.06,52.22 70.1,51.18 72.87,51.18 R12.1 ; R35.1 31.37,38.19 R34.1 31.88,38.7 v1(31.88,39.62)
  vias: v1(51.56,70.61) v1(51.56,69.6) v1(51.56,68.58) v1(51.56,67.56) v1(51.56,66.55) v1(51.56,65.53) v1(51.56,64.01) v1(51.56,62.99) v1(51.56,61.98) v1(51.56,60.96) v1(51.56,59.94) v1(51.56,58.93) v1(52.07,70.61) v1(52.07,69.6) v1(52.07,68.58) v1(52.07,67.56) v1(52.07,66.55) v1(52.07,65.53) v1(52.07,64.01) v1(52.07,62.99) v1(52.07,61.98) v1(52.07,60.96) v1(52.07,59.94) v1(52.07,58.93) v1(52.2,91.06) v1(52.2,87.25) v1(52.2,84.45) v1(52.2,80.64) v1(52.2,75.44) v1(52.2,74.42) v1(52.2,73.41) v1(52.2,72.39) v1(52.7,75.44) v1(52.7,74.42) v1(52.7,73.41) v1(52.7,72.39) v1(52.96,77.98) v1(52.96,76.96) v1(53.47,77.98) v1(53.47,76.96) v1(53.98,89.15) v1(53.98,82.55) v1(55.75,91.06) v1(55.75,87.25) v1(55.75,84.45) v1(55.75,80.64)
VIN2: length 62.5
  LAYER_2 w0.508: v1(48.77,13.08) 48.77,12.19
  LAYER_3 w0.508: v1(74.42,56.24) 74.42,41.91 48.77,16.26 v1(48.77,13.08)
  BOTTOM w0.254: U1.7 76.09,57.91 75.69,57.51 C11.1
  BOTTOM w0.508: R6.1 v1(48.77,13.08)
  BOTTOM w0.635: C11.1 v1(74.42,56.24) 73.28,55.09 R12.2
_N7: length 10.3
  BOTTOM w0.254: U1.9 74.44,60.22 74.17,59.94 74.17,59.31 72.61,57.75 71.59,57.75 71.03,57.19 C43.2 71.03,56.68 70.57,56.22 69.88,56.22 R47.2 R48.1
_N30: length 9.9
  LAYER_4 w0.254: v1(30.86,33.4) 30.86,27.18 31.39,26.65 v1(31.39,26.54)
  BOTTOM w0.254: U2.7 v1(31.39,26.54) ; U2.10 31.39,32.87 v1(30.86,33.4)
_N97: length 3.5
  BOTTOM w0.254: TP6.1 101.39,7.2 R1.1
_N98: length 5.9
  BOTTOM w0.254: U1.3 78.09,58.81 80.48,56.43 R13.1 R14.2
_N99: length 6
  BOTTOM w0.254: R4.2 85.3,4.23 86.16,3.38 88.83,3.38 JP2.3
_N100: length 61.1
  LAYER_3 w0.254: JP2.6 JP2.4 JP2.2 88.15,6.71 81.66,13.21 81.66,55.12 79.5,57.28 79.5,58.17 v1(79.63,58.29)
  BOTTOM w0.254: U1.2 78.59,59.08 79.38,58.29 v1(79.63,58.29)
_N104: length 79.9
  LAYER_3 w0.254: TP1.1 51.64,6.35 SW1.5 ; SW1.5 76.2,30.91 76.2,57.78 77.47,59.05 80.39,59.05 v1(81.03,59.69) ; SW1.5 SW1.2
  BOTTOM w0.254: v1(81.03,59.69) 80.5,60.22 U1.28
_N130: length 9.6
  BOTTOM w0.254: R56.1 52.15,10.5 C18.1 50.5,10.45 ; 50.5,10.45 50.42,10.38 SW1.4 SW1.1 ; 50.5,10.45 R6.2
_N143: length 63.9
  LAYER_3 w0.254: TP2.1 67.06,6.35 77.34,16.64 77.34,53.09 78.16,53.91 78.16,54.35 77.85,54.65 v1(77.85,57.53)
  BOTTOM w0.254: TP2.1 67.48,7.15 C4.1 67.52,9.57 R2.1 67.56,11.47 ; v1(77.85,57.53) 77.59,57.79 U1.4
_N148: length 10.3
  BOTTOM w0.254: U1.21 78.59,63.99 79.76,65.15 80.43,65.15 R8.1 81.7,67.9 C10.1 81.88,69.83 R7.2 81.85,71.83 C9.2
_N161: length 1.6
  BOTTOM w0.254: C13.2 78.61,69.56 R11.1
_N165: length 5
  BOTTOM w0.254: U1.20 78.09,64.25 78.74,64.9 78.74,66.26 C13.1 C12.1
_N173: length 10.3
  LAYER_3 w0.254: v1(77.85,70.61) 77.59,70.35 77.59,65.41 v1(77.85,65.15)
  BOTTOM w0.254: v1(77.85,70.61) 77.94,70.61 R9.2 R10.1 ; U1.19 77.59,64.89 v1(77.85,65.15)
_N186: length 69.7
  LAYER_3 w0.254: v1(81.03,58.04) 81.15,58.04 85.09,54.1 85.09,34.8 109.13,10.76 JP1.2
  BOTTOM w0.254: JP1.6 JP1.4 JP1.2 ; U1.1 79.09,59.36 79.4,59.05 80.01,59.05 v1(81.03,58.04)
_N192: length 87
  LAYER_3 w0.254: v1(76.96,70.51) v1(76.96,65.15) 77.6,64.52 80.14,64.52 83.44,61.21 83.44,59.94 88.65,54.74 88.65,39.62 TP7.1
  BOTTOM w0.254: v1(76.96,65.15) 77.09,65.02 U1.18 ; R15.1 v1(76.96,70.51) 76.86,70.51
_N215: length 9.7
  LAYER_4 w0.254: v1(86.36,60.96) 85.72,61.59 84.33,61.59 83.69,60.96 v1(81.79,60.96)
  BOTTOM w0.254: U1.26 81.53,61.22 v1(81.79,60.96) ; R17.1 R16.2 87.12,60.96 v1(86.36,60.96)
_N308: length 4.5
  TOP w0.635: R49.2 R24.2 69.35,78.27 C21.1
_N309: length 17.5
  BOTTOM w0.254: JP1.5 114.55,6.14 114.55,7.37 112.39,9.53 R1.2 103.04,9.57 C2.1
BG: length 50.8
  TOP w0.635: P3.1 77.47,75.56 v1(76.07,76.96) 76.09,76.98 76.09,78.24 76.07,78.26 ; Q2.4 v1(64.77,76.96)
  LAYER_5 w0.635: v1(68.83,61.59) 68.45,61.59 64.77,65.28 v1(64.77,76.96) 65.63,76.96 ; 65.63,76.96 65.63,66.32 v1(68.83,63.12) ; 65.63,76.96 v1(76.07,76.96)
  BOTTOM w0.635: v1(68.83,61.59) R19.2 ; R20.2 v1(68.83,63.12)
BG_X: length 3.5
  BOTTOM w0.254: U1.12 74.93,61.7 73.5,61.7 73.4,61.59
  BOTTOM w0.381: R19.1 73.4,61.59
BG_X3: length 3.9
  BOTTOM w0.254: 74.38,62.22 U1.13
  BOTTOM w0.381: 74.38,62.22 73.93,62.22 73.03,63.12 R20.1
DRVCC: length 14.3
  LAYER_3 w0.254: v1(71.81,56.08) 66.99,56.08 v1(65.66,57.4)
  BOTTOM w0.254: R25.2 65.66,58.38 v1(65.66,57.4) ; 75.45,59.57 U1.8
  BOTTOM w0.508: C15.1 v1(71.81,56.08) 71.95,56.08 75.45,59.57
DRVUV: length 8.3
  BOTTOM w0.254: R43.2 R44.1 83.82,57.15 82.04,58.93 82.04,59.69 81.01,60.72 U1.27
DTCA: length 11.8
  BOTTOM w0.254: R45.2 R46.1 86.87,56.64 85.34,58.17 84.07,58.17 83.27,58.97 C1.1 82.45,60.26 82.45,61.18 81.91,61.72 U1.25
DTCB: length 13.3
  BOTTOM w0.254: 83.27,61 C5.1 ; 83.27,61 82.06,62.22 U1.24 ; 83.27,61 83.27,61.18 84.07,61.98 88.56,61.98 R55.1 89.62,63.04 89.62,63.2 89.57,63.25 R54.2 89.57,64.9
EXTVCC: length 98.6
  LAYER_3 w0.254: v1(72.52,58.8) 72.52,51.31 59.82,38.61 27.56,38.61 v1(27.05,38.1) 26.04,38.1 24,36.07 24,19.18 v1(29.72,13.46)
  BOTTOM w0.254: v1(29.72,13.46) 29.78,13.46 R27.2 R28.1 30.71,10.38 C24.1 ; U1.10 74.18,60.72 72.52,59.05 v1(72.52,58.8) 72.3,58.59 71.45,58.59 C14.1 ; v1(27.05,38.1) R38.1
INTVCC: length 141.3
  LAYER_3 w0.254: v1(78.99,53.85) 80.14,52.7 80.14,12.57 87.99,4.72 JP2.1 88.17,4.54 89.66,3.05 107.46,3.05 JP1.1 ; v1(90.87,54.93) 90.87,55.31 v1(87.76,58.42) 87.76,60.58 v1(91.95,64.77)
  LAYER_4 w0.254: v1(76.2,72.9) 75.44,72.14 75.44,68.07 72.39,65.02 v1(72.39,60.07) 73.41,60.07 78.16,55.32 78.16,54.69 v1(78.99,53.85)
  BOTTOM w0.254: 88.39,53.54 89.48,53.54 v1(90.87,54.93) ; 88.39,53.54 R45.1 ; 88.39,53.54 85.34,53.54 ; R16.1 87.76,58.63 v1(87.76,58.42) ; 82.17,53.54 82.17,54.7 R14.1 ; 82.17,53.54 79.3,53.54 v1(78.99,53.85) 79.17,54.03 79.17,54.7 R52.1 ; 82.17,53.54 85.34,53.54 ; R43.1 85.34,53.54 ; R4.1 86.96,5.93 JP2.1 ; v1(91.95,64.77) 91.4,64.77 R54.1 ; C16.1 v1(72.39,60.07) 72.76,60.07 73.91,61.22 U1.11 ; R9.1 R15.2 76.87,72.9 v1(76.2,72.9)
SNSN: length 22.6
  TOP w0.508: J5.3 85.29,63.68 v1(85.06,63.68) ; J5.3 J5.2 J5.5 ; J5.3 J5.4
  LAYER_3 w0.254: v1(85.06,63.68) 86.28,63.68 88,65.39 v1(88,66.46)
  BOTTOM w0.254: C42.2 86.16,63.03 R5.2 84.41,63.08 C17.2 80.86,63.08 80.5,62.72 U1.23 ; R30.2 v1(88,66.46) R33.2
  BOTTOM w0.508: v1(85.06,63.68) 85.06,63.63 R5.2
SNSP: length 25.6
  TOP w0.254: J5.1 v1(84.33,65.41)
  LAYER_4 w0.254: v1(81.66,64.14) 81.66,75.69 v1(80.52,76.83)
  BOTTOM w0.254: v1(80.52,76.83) R29.2 ; v1(84.33,65.41) 84.33,64.86 R5.1 ; R5.1 84.41,64.68 C17.1 82.26,64.14 v1(81.66,64.14) 79.63,64.14 79.09,63.6 U1.22 ; R5.1 86.11,64.73 C41.1 86.23,64.68 86.23,65.53 85.47,66.29 R31.2
SW: length 9.1
  BOTTOM w0.254: U1.15 75.5,63.36 75.49,63.37
  BOTTOM w0.508: C19.2 68.3,67 R26.1 70.98,65.99 71.93,65.99 72.48,65.44 73.75,65.44 75.49,63.7 75.49,63.37
SWN: length 3.3
  BOTTOM w0.254: R29.1 80.16,80.75 v1(79.38,81.53)
  BOTTOM w0.508: v1(69.75,69.67) 69.98,69.44 R26.2 70.33,69.25 v1(70.33,69.67)
  vias: v1(60.83,85.72) v1(60.83,85.09) v1(61.47,85.72) v1(61.47,85.09)
TG: length 72.8
  TOP w0.635: v1(59.04,86.29) 59.04,85.61 R41.1 ; R3.1 v1(59.05,92.77) 59.05,92.9 59.37,93.22 P1.1
  LAYER_3 w0.635: v1(71.75,69.8) 71.03,70.52 64.48,70.52 59.04,75.96 v1(59.04,86.29) ; v1(73.66,69.85) 72.14,71.37 64.9,71.37 59.94,76.33 59.94,85.38 ; 59.05,92.71 v1(59.05,92.77) ; 59.05,92.71 59.05,92.65 59.04,92.63 v1(59.04,86.29) ; 59.05,92.71 59.94,91.82 59.94,85.38 ; v1(59.04,86.29) 59.94,85.38
  BOTTOM w0.635: R22.2 71.88,69.67 v1(71.75,69.8) ; v1(73.66,69.85) 73.79,69.72 R21.2
TG_X: length 5.1
  BOTTOM w0.254: U1.17 76.59,64.63 76.2,65.02
  BOTTOM w0.381: R21.1 74.23,67 76.2,65.02
TG_X1: length 1.6
  TOP w0.635: R3.2 59.05,91.07 Q3.4
TG_X2: length 1.7
  TOP w0.635: R41.2 58.94,84.47 Q1.4
TG_X3: length 6.2
  BOTTOM w0.254: U1.16 76.09,64.11 75.44,64.77
  BOTTOM w0.381: 75.44,64.77 74.12,66.09 72.79,66.09 R22.1
UNNAMED_2_ADLT7809_I6_BOOST: length 4.4
  BOTTOM w0.254: 74.88,62.79 U1.14
  BOTTOM w0.381: 75.03,62.79 74.73,62.79 72.87,64.64 R18.1
UNNAMED_2_ADLTC3639_I1_OVLO: length 5.4
  BOTTOM w0.254: R37.2 R35.2 31.55,34.86 32.39,34.02 U2.12
UNNAMED_2_ADLTC3639_I1_RUN: length 2.8
  BOTTOM w0.254: U2.14 33.39,33.42 33.91,33.94 R36.2
UNNAMED_2_CAP_I88_N1: length 5.2
  BOTTOM w0.508: R18.2 67.46,64.64 D1.C 66.64,65.21 C19.1
UNNAMED_2_CAP_I91_N1: length 3.7
  BOTTOM w0.508: R25.1 67.35,58.47 C20.1 67.35,61.15 67.27,61.23 R23.2
UNNAMED_2_CAP_I169_N1: length 16.3
  LAYER_3 w1.27: v1(38.61,36.32) 26.93,36.32 v1(25.53,34.92)
  LAYER_4 w0.254: v1(38.61,36.32) 38.99,36.32
  BOTTOM w0.254: 25.91,35.43 v1(25.84,35.37)
  BOTTOM w1.27: L2.2 38.99,36.32
  vias: v1(39.12,36.32)
UNNAMED_2_CNTP1P_I150_N1: length 4.3
  BOTTOM w0.254: R28.2 32.7,7.3 TP9.1
UNNAMED_2_DIO_I86_P: length 3
  BOTTOM w0.508: R23.1 65.57,63.08 64.24,64.41 D1.A
UNNAMED_2_IND_I113_N2: length 36.7
  TOP w0.254: v1(97.03,80.64) R32.1
  LAYER_3 w0.254: v1(97.03,80.64) 97.41,80.26 97.41,77.23 96.13,75.95 95.12,75.95 88.64,69.47 86,69.47 v1(85.47,68.93)
  LAYER_4 w0.508: v1(89.75,68.16) 89.75,69 86.74,72.01 86.74,80.9 v1(87.5,81.66)
  BOTTOM w0.254: 85.37,68.93 v1(85.47,68.93) R31.1
  BOTTOM w0.508: R30.1 v1(89.75,68.16)
UNNAMED_2_RES_I159_N2: length 2.5
  BOTTOM w0.254: R34.2 33.49,37.86 33.91,37.44 R36.1
VOUT: length 120.9
  TOP w0.254: R32.2 v1(98.42,80.64)
  LAYER_3 w0.254: v1(87.12,68.93) 88.75,68.93 88.82,69.01 88.83,69.01 95.26,75.44 96.27,75.44 97.98,77.15 97.98,80.2 v1(98.42,80.64)
  LAYER_3 w0.381: v1(32.7,13.52) 40.45,13.52 72.01,45.09 v1(72.01,48.51)
  LAYER_4 w0.381: v1(72.01,48.51) 87.88,48.51 v1(98.93,59.56)
  LAYER_4 w0.508: v1(87.76,74.3) v1(99.69,74.3)
  BOTTOM w0.254: R33.1 v1(87.12,68.93)
  BOTTOM w0.381: R27.1 v1(32.7,13.52)
  BOTTOM w0.508: R42.2 v1(87.76,74.3)
VPRG: length 5.1
  BOTTOM w0.254: U1.6 76.59,58.92 76.96,58.55 76.96,57.4 77.62,56.74 R53.1 R52.2
VSOP: length 4.5
  BOTTOM w0.254: R42.1 83.84,72.02 C9.1 83.7,69.9 R7.1

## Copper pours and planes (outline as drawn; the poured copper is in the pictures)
GND_POWER on TOP (solid shape): 79.63,59.82 75.18,59.82 75.18,63.25 79.63,63.25
GND_POWER on LAYER_2 (solid shape): 79.5,59.94 75.18,59.94 75.18,62.99 79.5,62.99
GND_POWER on LAYER_3 (solid shape): 79.5,59.82 75.06,59.82 75.06,63.12 79.5,63.12
GND_POWER on LAYER_4 (solid shape): 79.5,59.94 75.18,59.94 75.18,62.99 79.5,62.99
GND_POWER on TOP: 1.27,125.73 138.43,125.73 138.43,1.27 1.27,1.27 1.27,79.48 26.04,79.48 29.87,75.64 29.87,83.26 26.16,86.97 1.27,86.97
GND_POWER on BOTTOM: 1.4,125.86 1.4,1.27 138.43,1.27 138.43,125.86 ; 10 cut-outs
GND_POWER on LAYER_2: 1.4,125.86 1.4,1.27 138.43,1.27 138.43,125.86 ; 1 cut-out
GND_POWER on LAYER_3, LAYER_4: 1.4,125.86 1.4,1.27 138.43,1.27 138.43,125.86
GND_POWER on LAYER_5: 1.4,125.86 1.4,1.27 138.43,1.27 138.43,125.86 ; 7 cut-outs
GND_SIGNAL on BOTTOM: 79.25,74.17 69.98,74.17 62.48,66.67 62.48,53.21 66.17,49.53 90.55,49.53 93.98,52.96 93.98,76.58 81.66,76.58 ; 8 cut-outs
GND_SIGNAL on LAYER_5: 79.25,74.17 69.98,74.17 62.48,66.67 62.48,53.21 66.17,49.53 90.55,49.53 93.98,52.96 93.98,76.58 81.66,76.58
VIN on TOP: 1.27,116.33 50.67,116.33 56.26,110.74 56.26,60.72 53.99,58.42 35.18,58.42 32,61.59 32,74.42 30.48,75.95 30.48,83.31 26.42,87.38 1.27,87.38
VIN on BOTTOM: 33.15,28.45 33.15,26.29 32.77,25.91 31.75,25.91 31.75,22.35 32.13,21.97 33.91,21.97 33.91,28.45
VIN on BOTTOM: 1.4,116.2 1.4,79.88 25.53,79.88 32,73.41 32,61.98 35.56,58.42 54.12,58.42 56.26,60.58 56.26,110.62 50.67,116.2
VIN on LAYER_3: 1.4,108.08 1.4,80.01 19.68,80.01 19.68,108.08
SWN on TOP: 56.77,91.69 81.79,91.69 83.31,90.17 83.31,80.01 82.93,79.63 57.15,79.63 56.64,80.14 56.64,83.44 56.77,83.57 59.82,83.57 59.94,83.69 59.94,85.34 59.82,85.47 56.77,85.47
SWN on LAYER_4: 74.32,68.96 65.3,68.96 58.32,75.95 58.32,93.6 59.84,93.6 60.6,92.71 60.6,86.87 60.99,86.36 61.75,86.36 62,86.11 62,84.71 60.86,83.57 60.86,76.2 65.05,72.01 72.29,72.01 74.32,69.98
UNNAMED_2_ADLTC3639_I1_SW on BOTTOM: 34.29,28.45 34.29,26.04 35.43,24.89 42.67,24.89 43.43,25.65 43.43,27.94 42.93,28.45
UNNAMED_2_ADLTC3639_I1_VFB on BOTTOM: 28.57,32.89 28.57,29.72 28.83,29.46 29.84,29.46 30.1,29.72 30.1,30.86 30.48,31.24 31.11,31.24 31.11,32.89
UNNAMED_2_CAP_I169_N1 on BOTTOM: 24.51,35.69 24.51,29.21 25.15,28.57 27.43,28.57 27.69,28.83 27.69,30.86 28.19,31.37 28.19,35.43 27.81,35.81 24.64,35.81
UNNAMED_2_CAP_I169_N1 on BOTTOM: 38.23,37.59 38.23,35.31 43.05,35.31 43.05,37.59
UNNAMED_2_IND_I113_N2 on TOP: 86.23,89.92 86.23,77.98 86.87,77.34 96.77,77.34 96.9,77.47 96.9,89.53 96.14,90.3 86.61,90.3
VOUT on TOP: 98.55,88.01 98.55,76.58 98.04,76.07 98.04,59.18 108.08,59.18 112.78,63.88 112.78,71.63 116.08,74.93 138.43,74.93 138.43,107.82 118.36,107.82
VOUT on BOTTOM: 123.57,100.83 123.57,92.58 120.02,89.03 120.02,76.2 121.28,74.93 138.43,74.93 138.43,106.68 129.41,106.68

Small or netless copper shapes (teardrops, artwork), in the pictures only: 5 on TOP, 61 on BOTTOM, 43 on LAYER_3, 11 on LAYER_4

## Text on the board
Ref Des/Silkscreen Bottom: SYNCHRONOUS BUCK CONTROLLER | WIDE INPUT AND OUTPUT VOLTAGE | EVAL-LTC7897-AZ
User.Comments: JP2: INSTALL SHUNT ACROSS PINS 1-2. | JP1: INSTALL SHUNT ACROSS PINS 3-4. | SW1: ON
Ref Des/Silkscreen Top: 135V MAX | 16V to 100V | 12V/20A | VOUT | GND | WIDE INPUT AND OUTPUT VOLTAGE | SYNCHRONOUS BUCK CONTROLLER | EVAL-LTC7897-AZ
DISPLAY_TOP: FAB NOTES REVISION: 2ND NOVEMBER 2022 | 8.   IMPEDANCE REQUIREMENTS: IF NO STACKUP IS DEFINED, THE VENDOR IS ALLOWED TO ADJUST THE DIELECTRIC | 13.  PLATING SPECIFICATION: | 9.   FILLET OPTIONS TO ENHANCE RELIABILITY AT PAD JUNCTIONS WHERE SPACING PERMITS. | 10.  THIEVING: | 11.  LAYER TO LAYER REGISTRATION SHALL BE WITHIN 0.003 INCHES. | 12.  DRILL SIZES ARE FINISHED HOLE SIZES. ALL HOLES SHALL BE LOCATED WITHIN 0.005 INCHES DTP,UNLESS SPECIFIED. | 14.  SURFACE FINISH: | 15.  SOLDERMASK: | 1.   DIMENSIONS ARE IN INCHES (EXCEPT WHERE NOTED). | ALL DOCUMENTS & SPECIFICATIONS REFERRED TO BELOW SHOULD BE THE LATEST REVISIONS. | 2.  BOARD MATERIAL:(USE CHECKED ITEMS) | 3.   ALL LAMINATES & BONDING MATERIALS SHOULD BE SELECTED FROM IPC-4101 OR IPC-4103,(TG>170 DEGC TD>300 DEGC) | 4.   REFER TO IPC-6010 SERIES, CLASS 2 FOR FABRICATION. | 5.   REFER TO LAMINATION DIAGRAM FOR OVERALL BOARD THICKNESS, TOLERANCE APPLIES AFTER ALL LAMINATION AND PLATING | 6.   BOW & TWIST NOT TO EXCEED 0.0075 INCHES (0.75%) PER LINEAR INCH AND SHOULD BE MEASURED PER IPC-TM-650, METHOD 2.4.22. | 7.   ACCEPTABILITY PER ADI SPECIFICATION TST00115. | 16.  APPLY SILKSCREEN TO BOTH SIDES USING A NON-CONDUCTIVE, EPOXY BASED INK PER ARTWORK. | ( ) FILLETS ALLOWED | (X) FILLETS NOT ALLOWED | ( ) VENDOR MAY ADD THIEVING TO COMPENSATE FOR LOW COPPER DENSITY AREAS MAINTAINING A MINIMUM | (X) VENDOR MAY NOT ADD THIEVING TO COMPENSATE FOR LOW COPPER DENSITY AREAS. | (X) LPI | ( ) OTHER_________ | COLOR | (X) GREEN | ( ) OTHER________ | (X) WHITE | ( ) OTHER | HINDER PROPER SOLDER WICKING. BARREL RELIEF ON SOLDERMASK ALLOWED IN UNFILLED VIA IN PAD HOLES. | (X) REFER TO LAMINATION DIAGRAM FOR FINISHED COPPER WEIGHT/THICKNESS REQUIRMENTS | (X) IMMERSION GOLD (ENIG) 1.58-3.94 MICRO INCHES OVER 118-236 MICRO INCHES MIN. OF ELECTROLESS NICKEL PER IPC-4552 | ( ) OSP (ORGANIC SOLDERABILITY PRESERVATIVE) | ( ) IMMERSION SILVER | ( ) SOFT WIRE BONDABLE GOLD 30-50 MICRO INCHES OF SOFT WIRE | ( ) EDGE CONNECTOR FINGERS ARE TO BE PLATED WITH 100 MICRO-INCHES(.0001") OF LOW STRESS | THICKNESS & TRACE WIDTHS TO MEET THE IMPEDANCE REQUIREMENT. IF SPECIFIED, THE VENDOR MUST | TRACE WIDTH & SPACING THAT IMPACT THE REQUIREMENTS MUST HAVE WRITTEN APPROVAL FROM ADI. | MINIMUM BARREL PLATING OF 0.001 INCHES. PLATED HOLES SHALL NOT BE ROUGH OR IRREGULAR SO AS TO | SOLDERMASK OVER BARE COPPER OR BARE GOLD (BOTH SIDES) TO MEET IPC-SM-840. | IF PRESENT,DO NOT MODIFY SOLDERMASK DEFINED PADS (MASK OPENINGS LESS THAN COPPER PAD) WITHOUT APPROVAL. | MEET THE REQUIREMENTS LISTED IN THE IMPEDANCE TABLE. ANY ADJUSTMENT MADE TO THE DEFINED STACKUP, | PROCESSES. FINISHED THICKNESS MEASURED FROM TOP COPPER TO BOTTOM COPPER. | (X)  ISOLA 370HR OR S1000-2 OR IT180 OR EQUIVALENT | ( )  ISOLA-FR408HR OR EQUIVALENT | ( )  ISOLA IS410 | ( )  MEGTRON 6 | ( )  NELCO-4000-13 | ( )  ROGERS 4350B | ( ) ROGERS 3003 | ( ) ARLON 85N | ( ) EM370D | ( )  OTHER ________________________ | UL FLAMMABILITY RATING 94V-0. BOARD MATERIAL & CONSTRUCTION SHALL MEET THE REQUIREMENTS OF UL796/UL796F. | BONDABLE GOLD OVER 100-150 MICRO INCHES OF NICKEL | NICKEL UNDER 30 MICRO-INCHES (.0003') OF GOLD | 0.100 INCH CLEARANCE FROM ALL COPPER FEATURES, | THE STARTING COPPER WEIGHT/THICKNESS CAN VARY AS LONG AS THE FINISHED COPPER | WEIGHT/THICKNESS IS NOT LESS THAN THE SPECIFIED VALUE. | UNLESS OTHERWISE SPECIFIED | HOMOGENOUS MATERIALS IN THIS BOARD SHALL BE COMPLAINT WITH THE EU DIRECTIVE 2002/95/EC | WORKMANSHIP SHALL CONFORM TO IPC-A-600, CLASS 2. | 21.  INTENTIONAL SHORTS: | 17.  FINAL ELECTRICAL TEST TO BE PERFORMED USING PROVIDED IPC-D-356A NETLIST OR ODB++ FORMAT FILE. | 22.  PEMNUTS: | 23.  MANUFACTURER TO ETCH/STAMP WITH PERMANENT NON-CONDUCTIVE INK | ON SECONDARY SIDE UNLESS OTHERWISE SPECIFIED: | 18.  A TIME DOMAIN REFLECTOMETER REPORT (TDR) FOR EACH IMPEDANCE CONTROLLED LAYER & A CERTIFICATE | 19.  IF PRESENT, ALL BLIND/BURIED VIAS WITH AN ASPECT RATIO <1:1 TO BE PLATED SHUT WITH COPPER WHEN | 20.  FOR VIA FILL INFORMATION REFER TO DRILL CHART: | 25. PANELIZATION: | 27.  MINIMUM DESIGN LINE WIDTH IS .006 INCH. | 28.  MINIMUM DESIGN LINE SPACING IS .006 INCH. | IS ACCEPTABLE, ALL OTHER INSTANCES MUST BE REPORTED. | IF AN INTENTIONAL SHORT REPORT IS SUPPLIED AND DOES NOT MATCH THE FAB DATA THEN | THE PCB SHALL HAVE A VERIFICATION STAMP. | ( )  NON-CONDUCTIVE EPOXY FILL ALL 0.XXXX INCHES DRILLED VIAS | ( )  COPPER FILL ALL 0.XXXX INCHES DRILLED VIAS | ( ) PEMNUTS TO BE INSTALLED BY FABRICATOR | ( ) PEMNUTS NOT TO BE INSTALLED BY FABRICATOR | (X) NOT APPLICABLE | USED AS VIA-IN-PAD OR AS A STACKED VIA. BLIND/BURIED VIAS WITH AN ASPECT RATIO >1:1 TO BE FILLED | A. UL CODE-FLAMMABILITY RATING FOR THOSE APPROVED MATERIALS(IF APPLICABLE) | B. DATE CODE | C. LOT NUMBER | D. MANUFACTURER LOGO | BOARDS TO BE SHIPPED IN ARRAY AND KEPT INTACT | PANEL TO BE SUBJECTED TO CUSTOMERS APPROVAL | PANEL SOLDER PASTE STENCIL GERBER TO BE PROVIDED TO ANALOG | CAN'T BE PERFORMED BECAUSE THE TRACE LENGTH IS TOO SHORT ON THE OUTER LAYERS AT THE PIN ESCAPES | ADI APPROVAL IS REQUIRED. | OF COMPLIANCE SHALL BE PROVIDED BY VENDOR AT TIME OF SHIPMENT. INSTANCES WHERE TDR TESTING | WITH NON-CONDUCTIVE EPOXY. | TOOLING: | FINISH: | NOTES: | MATERIAL: | TESTING: | MISCELLANEOUS:
DIMENSION: "0"
PAGE_OUTLINE: -083560
User.17: 08-      -07 | L2 GND/SIGNAL
User.18: 08-      -08 | L3 GND/SIGNAL
User.19: L4 GND/SIGNAL | 08-      -09
User.20: L5 GND/SIGNAL | 08-      -10
User.24: SUPPLY | POWER | CONNECT EN/UVLO | TO GND FOR SHUTDOWN | OPTIONAL | OPTIONAL FOR SYNC | IN | OUT | V | LOAD | I | A | - | +
User.45: FIGURE | SIZE | 10.0 | 35.0 | 40.0 | 100.0 | 191.0 | 213.0 | 187.0 | PLATED | NON-PLATED | DRILL CHART: TOP to BOTTOM | ALL UNITS ARE IN MILS | QTY | 247 | 22 | 4 | 11 | 2 | TOLERANCE/NOTES
